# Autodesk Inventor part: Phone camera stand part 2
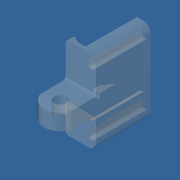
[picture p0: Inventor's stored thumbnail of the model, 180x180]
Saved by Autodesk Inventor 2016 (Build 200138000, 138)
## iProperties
Created: 2016-02
Part Number: Phone camera stand part 2
Material: PMMA Plastic
Document SubType Name: Modeling
Designer: Miha
Density: 1.188 g/cm^3
Appearance: Polycarbonate - Clear
Mass: 27.2607 g
Surface Area: 117.819 cm^2
Volume: 22.9467 cm^3
Author: Miha
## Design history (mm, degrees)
sketch "Sketch1"
  geometry: L1 (0, 0)-(40, 0); L2 (40, 0)-(40, -60); L3 (40, -60)-(0, -60); L4 (0, -60)-(0, 0)
  constraints: 8 end point, 2 parallel, 1 horizontal, 1 perpendicular
  dimensions: "d0" = 40 distance of L2.end L3.end; "d1" = 60 distance of L1.end L2.end
extrude "Extrusion1" new body sketch "Sketch1" distance "d2" = 3; taper "d3" = 0 deg
sketch "Sketch2"
  geometry: L1 (3, 0)-(3, 60) reference; L2 (3, 60)-(10, 60); L3 (10, 60)-(10, 45); L4 (10, 45)-(3, 45); L5 (3, 45)-(3, 60); L6 (3, 0)-(10, 0); L7 (10, 0)-(10, 15); L8 (10, 15)-(3, 15); L9 (3, 15)-(3, 0); 1 further point
  constraints: 16 end point, 4 parallel, 2 horizontal, 2 perpendicular
  dimensions: "d6" = 7 distance of L3.end L4.end; "d7" = 15 distance of L2.end L3.end; "d10" = 7 distance of L8.end L7.end; "d11" = 15 distance of L7.end L6.end
extrude "Extrusion2" join sketch "Sketch2" stored distance "d8" = 3; taper "d9" = 0 deg
sketch "Sketch5"
  geometry: L1 (-60, 40)-(-60, 0) reference; L2 (-60, 0)-(0, 0); L3 (0, 0)-(0, 3); L4 (0, 3)-(-60, 3); L5 (-60, 3)-(-60, 0); 1 further point
  constraints: 8 end point, 2 parallel, 1 horizontal, 1 perpendicular
  dimensions: "d17" = 3 distance of L3.end L2.end
extrude "Extrusion4" join sketch "Sketch5" distance "d18" = 12; taper "d19" = 0 deg
sketch "Sketch7"
  geometry: L1 (10, 15)-(3, 15) reference; L2 (3, 15)-(3, 0); L3 (6.45, 7.5)-(6.45, 4.9); L4 (6.45, 4.9)-(3, 4.9); L5 (3, 4.9)-(3, 10.5); L6 (3, 10.5)-(6.45, 10.5); L7 (6.45, 10.5)-(6.45, 4.9); L8 (3, 45)-(3, 15) reference; L9 (3, 30)-(-11.965, 30); L10 (6.45, 52.5)-(6.45, 55.1); L11 (6.45, 55.1)-(3, 55.1); L12 (3, 55.1)-(3, 49.5); L13 (3, 49.5)-(6.45, 49.5); L14 (6.45, 49.5)-(6.45, 55.1); 1 further point
  constraints: 24 end point, 5 symmetric about line, 2 horizontal, 2 parallel, 1 midpoint, 1 perpendicular, 1 vertical
  dimensions: "d83" = 5.6 distance between parallel lines of L6 L4; "d84" = 3.45 distance from line of L3.start L2
extrude "Extrusion6" cut sketch "Sketch7" distance "d31" = 39; taper "d32" = 0 deg
workplane "Work Plane1"
mirror "Mirror1"
sketch "Sketch10"
  geometry: L1 (-7, 11)-(-7, 41) reference; L2 (-7, 26)-(-7, -4); L3 (-8.5, 26)-(-8.5, -4); L4 (-7, -4)-(3.698, -4); L5 (3.698, -4)-(3.698, 57.12); L6 (3.698, 57.12)-(-7, 57.12); L7 (-7, 57.12)-(-7, -4); 3 further points
  constraints: 12 end point, 4 equal length, 1 horizontal, 1 midpoint, 1 perpendicular
  dimensions: "d46" = 1.5 distance between parallel lines of L2 L3
extrude "Extrusion9" cut sketch "Sketch10" stored distance "d47" = 30; taper "d48" = 0 deg
sketch "Sketch11"
  geometry: L1 (-60, 40)-(-60, 3) reference; L2 (0, 0)-(-60, 0); L3 (-60, 0)-(-60, 3); L4 (-60, 3)-(0, 3); L5 (0, 3)-(0, 0)
  constraints: 8 end point, 2 parallel, 1 horizontal, 1 perpendicular
extrude "Extrusion10" join sketch "Sketch11" distance "d49" = 7; taper "d50" = 0 deg
fillet "Fillet4" dims "d51" = 4
fillet "Fillet5" dims "d52" = 6
sketch "Sketch12"
  geometry: L1 (-12, -3)-(-12, 0) reference; L2 (-12, 0)-(-12, 4); L3 (-12, 0)-(-8, 0); L4 (0, 0)-(-12, 0) reference; L5 (-12, 0)-(-4.9, 0); A1 r 12.885 centre (-2.45, 12.65) between (-12, 4) and (-4.9, 0); 1 further point
  constraints: 6 end point, 2 point on circle, 1 centre point, 1 horizontal, 1 perpendicular, 1 point on line, 1 vertical
  dimensions: "d53" = 4 distance of L1.end L2.end; "d54" = 90 deg angle of L3 L2 (derived)
extrude "Extrusion11" join sketch "Sketch12" stored distance "d55" = 7; taper "d56" = 0 deg
sketch "Sketch13"
  geometry: L1 (-41.063, 3)-(-19, 3) reference; L2 (-30.031, 3)-(-32.531, 3); L3 (-32.531, 3)-(-32.531, 18); L4 (-32.531, 18)-(-30.031, 18); L5 (-30.031, 18)-(-30.031, 3); 1 further point
  constraints: 8 end point, 2 parallel, 1 horizontal, 1 midpoint, 1 perpendicular
  dimensions: "d57" = 2.5 distance of L3.end L4.end; "d58" = 15 distance of L2.end L3.end
extrude "Extrusion12" join sketch "Sketch13" distance "d59" = 5; taper "d60" = 0 deg
sketch "Sketch14"
  geometry: L1 (5, 15)-(5, 0) reference; L2 (5, 2.773)-(3.734, 2.773); L3 (3.734, 2.773)-(0, 4.075); L4 (0, 0)-(0, 15) reference; L5 (0, 4.075)-(0, 0); L6 (5, 0)-(0, 0) reference; L7 (0, 0)-(5, 0); L8 (5, 0)-(5, 2.773); L9 (5, 2.773)-(5, 7.5); L10 (0, 15)-(5, 15) reference; L11 (0, 15)-(5, 7.5); L12 (5, 15)-(5, 7.5); L13 (5, 15)-(0, 15); 1 further point
  constraints: 18 end point, 2 collinear, 2 horizontal, 2 point on line, 1 midpoint, 1 perpendicular, 1 vertical
extrude "Extrusion13" cut sketch "Sketch14" distance "d61" = 5; taper "d62" = 0 deg
mirror "Mirror3"
fillet "Fillet7" dims "d65" = 1
sketch "Sketch15"
  geometry: L1 (19, 18.937)-(22, 18.937); L2 (22, 18.937)-(22, 22.937); L3 (22, 22.937)-(19, 22.937); L4 (19, 22.937)-(19, 18.937); L5 (22, 22.937)-(0, 22.937); L6 (0, 22.937)-(0, 34.637); L7 (0, 34.637)-(22, 34.637); L8 (22, 34.637)-(22, 22.937); 1 further point
  constraints: 16 end point, 4 parallel, 2 horizontal, 2 perpendicular
  dimensions: "d66" = 3 distance of L3.end L2.end; "d67" = 4 distance of L2.end L1.end; "d68" = 22 distance of L6.end L7.end; "d69" = 11.7 distance of L5.end L6.end
extrude "Extrusion14" join sketch "Sketch15" distance "d70" = 30; taper "d71" = 0 deg
sketch "Sketch16"
  geometry: L1 (22, 0)-(0, 0) reference; L2 (11, 0)-(11, -15); L3 (11, 0)-(26, 0); L4 (0, 0)-(0, -30) reference; L5 (0, -18.354)-(0, -30); L6 (22, -30)-(0, -30) reference; L7 (0, -30)-(22, -30); L8 (22, -30)-(22, -18.354); L9 (22, 0)-(22, -30) reference; C1 r 4.2 at (11, -15); A1 r 11.5 centre (11, -15) between (0, -18.354) and (22, -18.354); 1 further point
  constraints: 10 end point, 2 centre point, 2 coincident, 2 perpendicular, 2 point on circle, 2 point on line, 1 collinear, 1 horizontal, 1 midpoint, 1 vertical
  dimensions: "d72" = 15 distance of L2.start L2.end; "d73" = 90 deg angle of L2 L3 (derived); "d74" = 8.4 diameter of C1; "d76" = 23 diameter of A1
extrude "Extrusion15" cut sketch "Sketch16" distance "d77" = 30; taper "d78" = 0 deg
fillet "Fillet8" dims "d79" = 2
fillet "Fillet9" dims "d80" = 2
fillet "Fillet10" dims "d81" = 1
fillet "Fillet11" dims "d82" = 0.75
body "Solid1"
other parameters: "d45" = -1.5
